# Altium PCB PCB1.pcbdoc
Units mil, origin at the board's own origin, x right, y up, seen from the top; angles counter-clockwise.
Board outline 3937.01 x 3937.01 mil, 2 copper layers (Top Layer, Bottom Layer), stack 62.206 mil thick; 20 components, 19 nets, 119 pads, 8 vias.
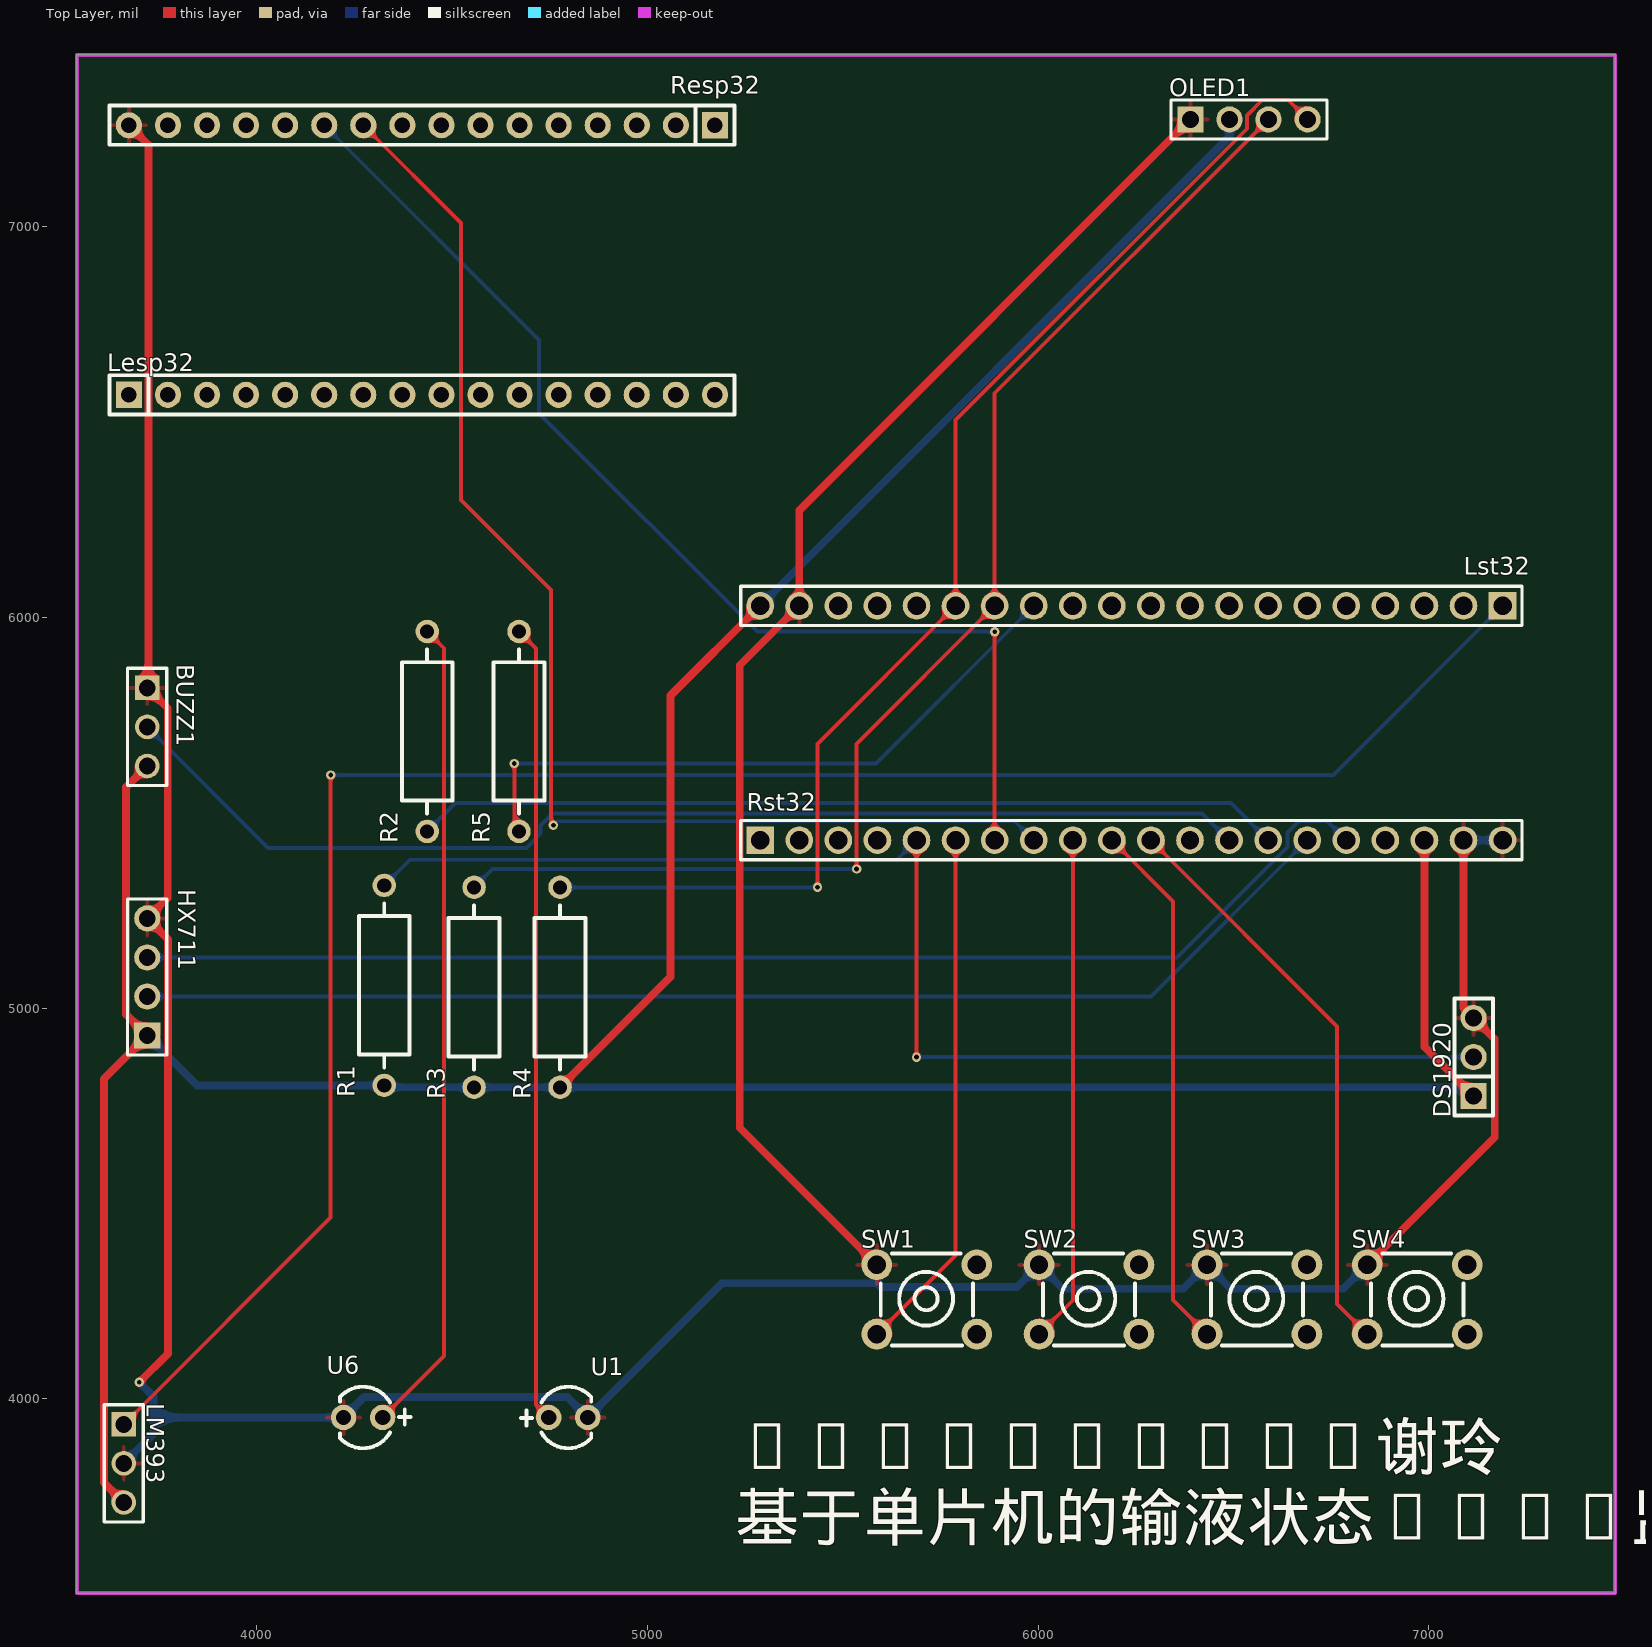
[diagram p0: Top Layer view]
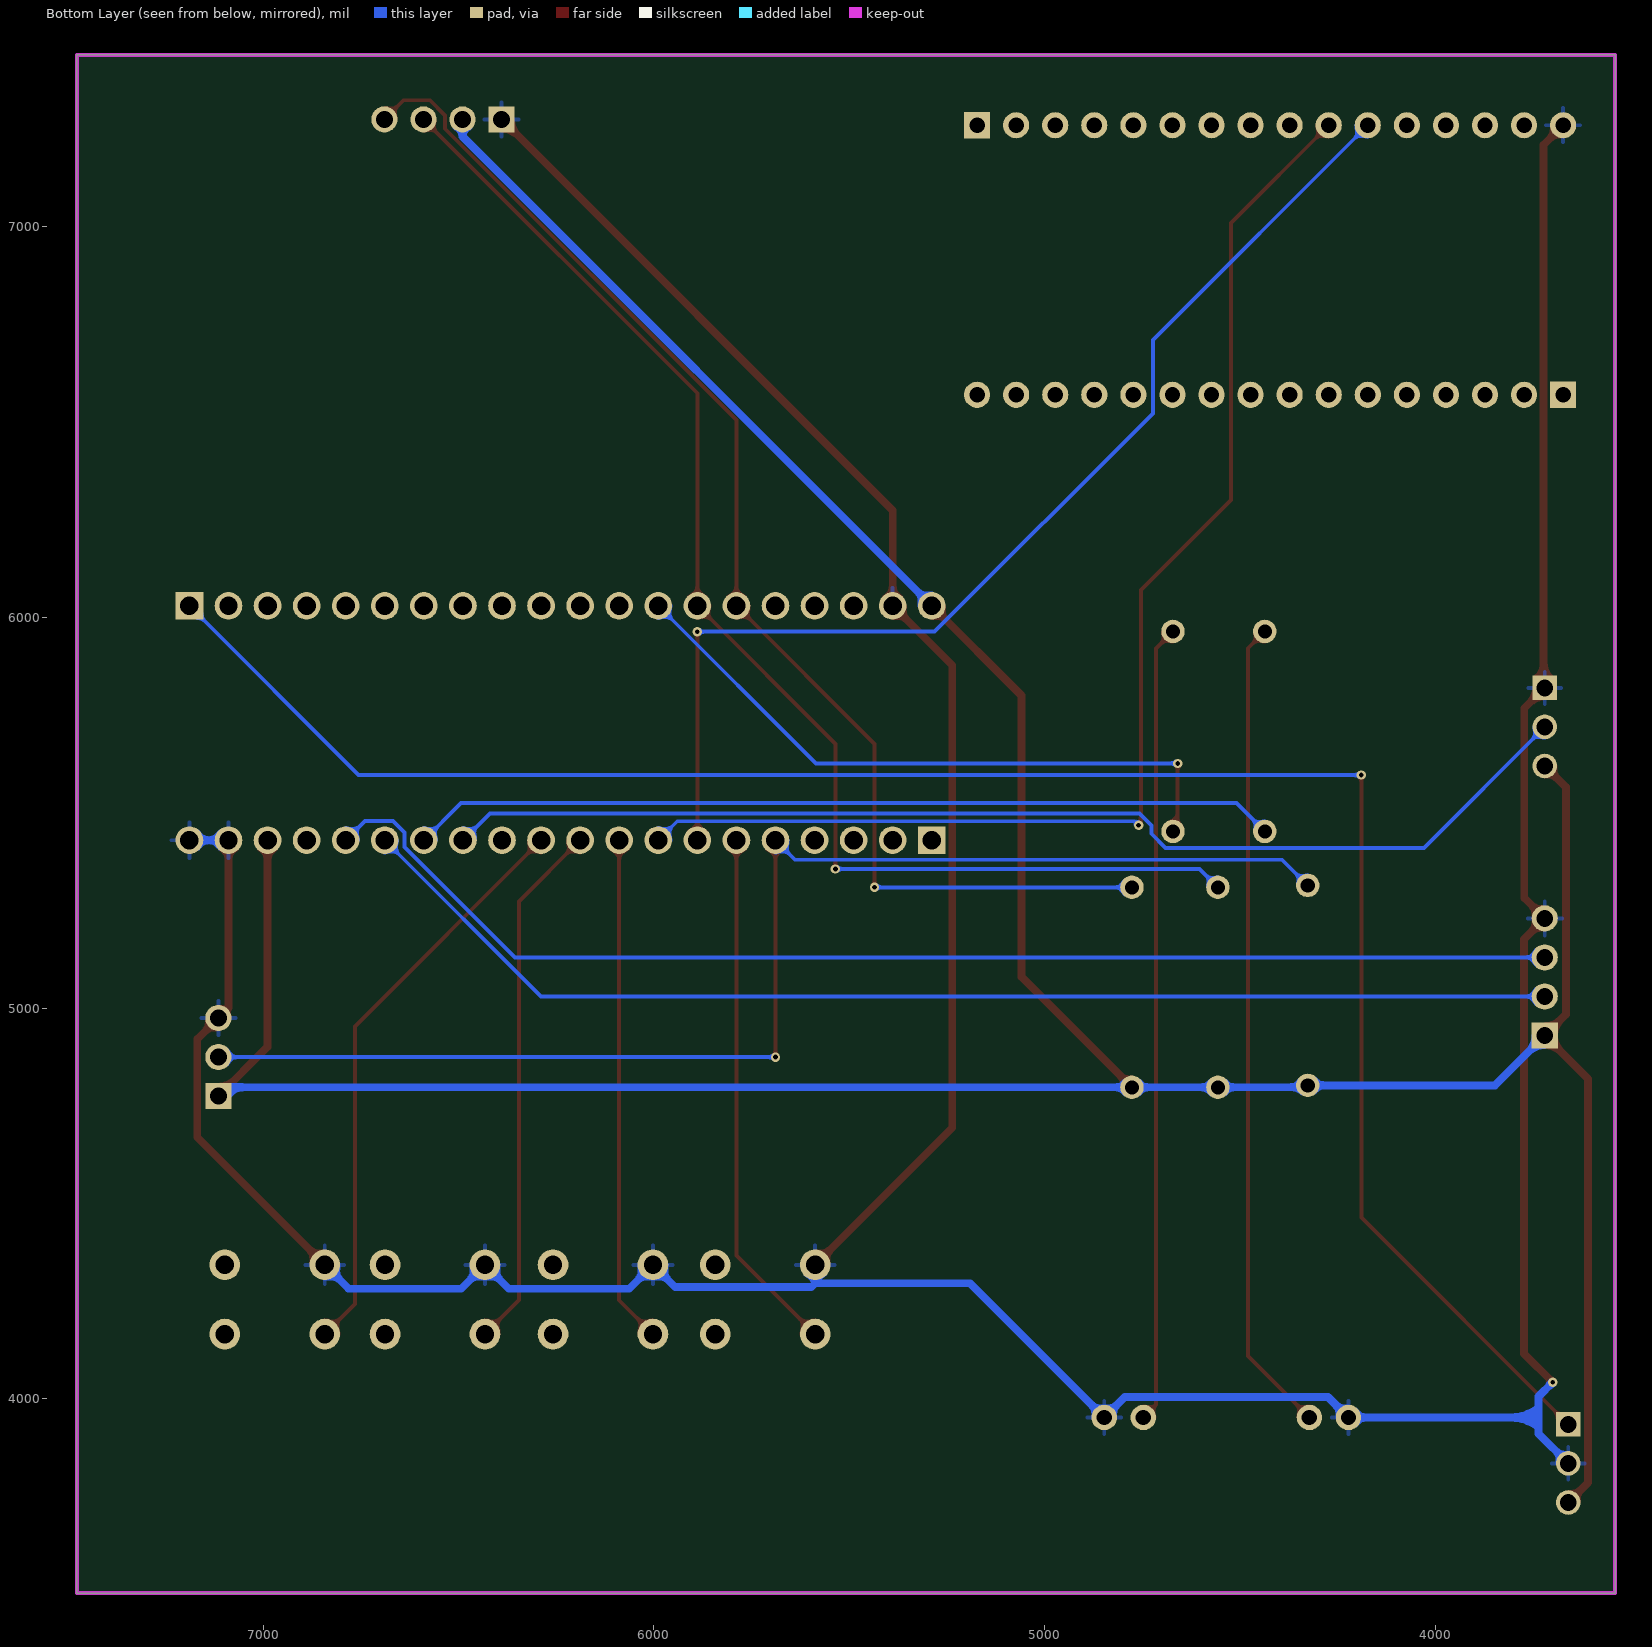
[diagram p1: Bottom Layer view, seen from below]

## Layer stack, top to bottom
Top Solder Mask Layer: solder mask 0.394, Dk 3.3
Top Layer: signal copper 1.379
Dielectric1: surface 59.449, FR4, Dk 4.5
Bottom Layer: signal copper 1.378
Bottom Solder Mask Layer: solder mask 0.394, Dk 3.3

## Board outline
3540,7440 3540,3502.99 7477.01,3502.99 7477.01,7440

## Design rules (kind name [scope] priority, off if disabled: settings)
BoardOutlineClearance copperThickness2oz_1 [All] p2: genericclearance=10 ignorepadtopadclearanceinfootprint=FALSE except(0: Arc-SplitContinuation Track-SplitContinuation SMDPad-SplitContinuation THPad-SplitContinuation Via-SplitContinuation Fill-SplitContinuation Region-SplitContinuation Poly-SplitContinuation Text-SplitContinuation Hole-SplitContinuation; 5.98: Arc-CutoutEdge SMDPad-CutoutEdge THPad-CutoutEdge Via-CutoutEdge Fill-CutoutEdge Region-CutoutEdge Text-CutoutEdge; 6.93: Hole-OutlineEdge Hole-CutoutEdge; 10: Poly-OutlineEdge Poly-CutoutEdge; 11.81: Arc-OutlineEdge Track-OutlineEdge SMDPad-OutlineEdge THPad-OutlineEdge Via-OutlineEdge Fill-OutlineEdge Region-OutlineEdge Text-OutlineEdge Track-CutoutEdge)
BoardOutlineClearance copperThickness1oz_1 [All] p4: genericclearance=8 ignorepadtopadclearanceinfootprint=FALSE except(0: Arc-SplitContinuation Track-SplitContinuation SMDPad-SplitContinuation THPad-SplitContinuation Via-SplitContinuation Fill-SplitContinuation Region-SplitContinuation Poly-SplitContinuation Text-SplitContinuation Hole-SplitContinuation; 6: SMDPad-CutoutEdge THPad-CutoutEdge Via-CutoutEdge Fill-CutoutEdge Region-CutoutEdge Text-CutoutEdge; 6.93: Hole-OutlineEdge Hole-CutoutEdge; 10: Poly-OutlineEdge Poly-CutoutEdge; 11.8: Arc-OutlineEdge Track-OutlineEdge SMDPad-OutlineEdge THPad-OutlineEdge Via-OutlineEdge Fill-OutlineEdge Region-OutlineEdge Text-OutlineEdge; 11.81: Arc-CutoutEdge Track-CutoutEdge)
Clearance copperThickness2oz [(InNet('3V3') OR InNet('GND'))] p1: gap=10 ignorepadtopadclearanceinfootprint=FALSE except(5.98: SMDPad-Track SMDPad-SMDPad THPad-Track SMDPad-THPad THPad-THPad Track-Via SMDPad-Via THPad-Via Via-Via Fill-Track Region-Track Fill-SMDPad Region-SMDPad Fill-THPad Region-THPad Fill-Via Region-Via Fill-Fill Fill-Region Region-Region Arc-Track Arc-SMDPad Arc-THPad Arc-Via Fill-Arc Region-Arc Arc-Arc Text-Track SMDPad-Text Text-THPad Text-Via Fill-Text Region-Text Arc-Text Text-Text; 6.93: Hole-Track Hole-SMDPad Hole-THPad Hole-Via Fill-Hole Region-Hole Hole-Arc Hole-Text)
Clearance copperThickness1oz [All] p3: gap=8 ignorepadtopadclearanceinfootprint=FALSE except(5.98: SMDPad-Track SMDPad-SMDPad THPad-Track SMDPad-THPad THPad-THPad Track-Via SMDPad-Via THPad-Via Via-Via Fill-Track Region-Track Fill-SMDPad Region-SMDPad Fill-THPad Region-THPad Fill-Via Region-Via Fill-Fill Fill-Region Region-Region; 6: Arc-Track Arc-SMDPad Arc-THPad Arc-Via Fill-Arc Region-Arc Arc-Arc Text-Track SMDPad-Text Text-THPad Text-Via Fill-Text Region-Text Arc-Text Text-Text; 6.93: Hole-Track Hole-SMDPad Hole-THPad Hole-Via Fill-Hole Region-Hole Hole-Arc Hole-Text; 10: Poly-Track Poly-SMDPad Poly-THPad Poly-Via Poly-Fill Poly-Region Poly-Poly Poly-Arc Poly-Text Poly-Hole)
Creepage creepage [All] p1: checkdistance=0 ignoreinternallayers=TRUE applytopolygonpour=TRUE
DiffPairsRouting differentialPair [All] p1: maxlimit=6 minlimit=6 mostfreqgap=6 toplayer_minwidth=5 toplayer_prefwidth=10 toplayer_maxwidth=100 toplayer_mingap=6 toplayer_prefgap=6 toplayer_maxgap=6 bottomlayer_minwidth=5 bottomlayer_prefwidth=10 bottomlayer_maxwidth=100 bottomlayer_mingap=6 bottomlayer_prefgap=6 bottomlayer_maxgap=6 maxuncoupledlength=10
HoleToHoleClearance otherClearance [All] p1: gap=11.81 allowstackedmicrovias=TRUE
Length netLength [All] p1: minlimit=0 maxlimit=0
MatchedLengths netLengthTolerance [All] p1: tolerance=1000
PasteMaskExpansion pasteMaskExpansion [All] p1: expansion=0
PlaneConnect innerPlane [All] p1: planeconnectstyle=Relief reliefexpansion=20 reliefentries=4 reliefconductorwidth=10 reliefairgap=10
PolygonConnect copperRegion [(InNet('GND'))] p1: connectstyle=Relief reliefconductorwidth=10 reliefentries=4 polygonreliefangle="90 Angle" airgapwidth=10 via.connectstyle=Relief via.reliefconductorwidth=10 via.reliefentries=4 via.polygonreliefangle="90 Angle" via.airgapwidth=10
RoutingVias viaSize [All] p1: holewidth=12.01 width=24.02 viastyle="Through Hole" minholewidth=11.81 minwidth=19.68 maxholewidth=248.03 maxwidth=393.7
SolderMaskExpansion solderMaskExpansion [IsVia] p1: expansion=-1000 istentingtop=TRUE
SolderMaskExpansion solderMaskExpansion [All] p2: expansion=2 istentingtop=FALSE
Width copperThickness2oz_2 [(InNet('3V3') OR InNet('GND'))] p1: maxlimit=10 minlimit=10 preferedwidth=10 toplayer_minwidth=20 toplayer_maxwidth=100 toplayer_prefwidth=20 bottomlayer_minwidth=20 bottomlayer_maxwidth=100 bottomlayer_prefwidth=20
Width copperThickness1oz_2 [All] p2: maxlimit=10 minlimit=10 preferedwidth=10 toplayer_minwidth=10 toplayer_maxwidth=100 toplayer_prefwidth=10 bottomlayer_minwidth=10 bottomlayer_maxwidth=100 bottomlayer_prefwidth=10

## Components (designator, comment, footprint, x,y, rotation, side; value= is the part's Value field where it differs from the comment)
BUZZ1 "PIN3" HDR-TH_3P-P2.54-V-M-1 3720,5720 r270 top
DS1920 "DS1920" HDR-TH_3P-P2.54-V-M 7115,4875 r90 top
HX711 "HX711" HDR-TH_4P-P2.54-V-M-1 3720,5080 r90 top
Lesp32 "Lesp32" HDR-TH_1X16P 4422.96,6570 r0 top
LM393 "LM393" HDR-TH_3P-P2.54-V-M-1 3660,3835 r270 top
Lst32 "Lst32" HDR-TH_HMT-PM254-1X20Z-H85 6239,6030 r180 top
OLED1 "2.54-1*4" HDR-TH_4P-P2.54-V-M-1 6540,7275 r0 top
R1 "4.7kΩ" RES-TH_BD3.3-L9.0-P13.00-D0.6 4326.6,5058.4 r90 top
R2 "220Ω" RES-TH_BD3.3-L9.0-P13.00-D0.6 4436.6,5708.4 r90 top
R3 "4.7kΩ" RES-TH_BD3.3-L9.0-P13.00-D0.6 4556.6,5053.4 r90 top
R4 "4.7kΩ" RES-TH_BD3.3-L9.0-P13.00-D0.6 4776.6,5053.4 r90 top
R5 "220Ω" RES-TH_BD3.3-L9.0-P13.00-D0.6 4671.6,5708.4 r90 top
Resp32 "Resp32" HDR-TH_1X16P 4423.04,7260 r180 top
Rst32 "Rst32" HDR-TH_HMT-PM254-1X20Z-H85 6239,5430 r0 top
SW1 "轻触开关6*6*4.5" KEY-TH_4P-L6.0-W6.0-P4.50-LS7.5 5715.45,4254.55 r0 top
SW2 "轻触开关6*6*4.5" KEY-TH_4P-L6.0-W6.0-P4.50-LS7.5 6130.45,4254.55 r0 top
SW3 "轻触开关6*6*4.5" KEY-TH_4P-L6.0-W6.0-P4.50-LS7.5 6560.45,4254.55 r0 top
SW4 "轻触开关6*6*4.5" KEY-TH_4P-L6.0-W6.0-P4.50-LS7.5 6970.45,4254.55 r0 top
U1 "LED_YELLOW" LED-TH_BD4.0-P2.54-FD_RED 4797.5,3952.5 r0 top
U6 "LED_RED" LED-TH_BD4.0-P2.54-FD_RED 4272.5,3952.5 r180 top

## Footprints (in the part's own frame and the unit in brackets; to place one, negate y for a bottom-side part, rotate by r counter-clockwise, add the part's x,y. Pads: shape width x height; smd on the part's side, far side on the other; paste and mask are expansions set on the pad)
HDR-TH_1X16P [mm]
  rect 1.7x1.7 hole 1 paste+0 mask+0.051: 1(-19.05,0)
  round 1.7 hole 1 paste+0 mask+0.051: 2(-16.51,0) 3(-13.97,0) 4(-11.43,0) 5(-8.89,0) 6(-6.35,0) 7(-3.81,0) 8(-1.27,0) 9(1.27,0) 10(3.81,0) 11(6.35,0) 12(8.89,0) 13(11.43,0) 14(13.97,0) 15(16.51,0) 16(19.05,0)
  silkscreen extent -20.32,-1.27 20.32,1.27
HDR-TH_3P-P2.54-V-M [mm]
  rect 1.7x1.7 hole 1.1: 1(-2.54,0)
  round 1.7 hole 1.1: 2(0,0) 3(2.54,0)
  silkscreen extent -3.81,-1.25 3.81,1.25
HDR-TH_3P-P2.54-V-M-1 [mm]
  rect 1.575x1.6 hole 1.1 paste+0 mask+0.05: 1(-2.54,0)
  round 1.6 hole 1.1 paste+0 mask+0.05: 2(0,0) 3(2.54,0)
  silkscreen extent -3.81,-1.27 3.81,1.27
HDR-TH_4P-P2.54-V-M-1 [mm]
  rect 1.7x1.7 hole 1.1: 1(-3.81,0)
  round 1.7 hole 1.1: 2(-1.27,0) 3(1.27,0) 4(3.81,0)
  silkscreen extent -5.08,-1.27 5.08,1.27
HDR-TH_HMT-PM254-1X20Z-H85 [mm]
  rect 1.8x1.8 hole 1.2: 1(-24.13,0)
  round 1.8 hole 1.2: 2(-21.59,0) 3(-19.05,0) 4(-16.51,0) 5(-13.97,0) 6(-11.43,0) 7(-8.89,0) 8(-6.35,0) 9(-3.81,0) 10(-1.27,0) 11(1.27,0) 12(3.81,0) 13(6.35,0) 14(8.89,0) 15(11.43,0) 16(13.97,0) 17(16.51,0) 18(19.05,0) 19(21.59,0) 20(24.13,0)
  silkscreen extent -25.4,-1.27 25.4,1.27
KEY-TH_4P-L6.0-W6.0-P4.50-LS7.5 [mm]
  round 2 hole 1.2: 1(-3.25,-2.25) 2(3.25,-2.25) 3(3.25,2.25) 4(-3.25,2.25)
  silkscreen extent -3,-3 3,3
LED-TH_BD4.0-P2.54-FD_RED [mil]
  round 65 hole 39.37: 1(-50,0) 2(50,0)
  silkscreen extent -122,-79 59,79
RES-TH_BD3.3-L9.0-P13.00-D0.6 [mil]
  round 60 hole 36: 1(-255.91,0) 2(255.9,0)
  silkscreen extent -210,-65 210,65

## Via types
v1: diameter 24.02, hole 12, Top Layer to Bottom Layer, 8 vias

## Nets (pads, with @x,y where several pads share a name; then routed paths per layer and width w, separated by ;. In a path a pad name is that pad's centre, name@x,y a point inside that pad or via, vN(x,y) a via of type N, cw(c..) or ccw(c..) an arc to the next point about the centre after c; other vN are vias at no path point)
3V3: BUZZ1.3 DS1920.1 HX711.1 LM393.3 Lst32.20 OLED1.2 R1.1 R3.1 R4.1 Rst32.18 | length 9350.6
  Top Layer w20: LM393.3 3609.03,3785.97 3609.03,4819.03 HX711.1 3665.85,4984.15 3665.85,5565.85 BUZZ1.3 ; R4.1 5059.27,5080.18 5059.27,5800.27 Lst32.20 ; Rst32.18 6989,4901.01 DS1920.1
  Bottom Layer w20: HX711.1 3847.5,4802.5 R1.1 4331.59,4797.5 R3.1 R4.1 7092.5,4797.5 DS1920.1 ; Lst32.20 6490,7231 OLED1.2
$1N10: R2.2 U6.1 | length 2094.8
  Top Layer w10: U6.1 4479.68,4109.68 4479.68,5921.22 R2.2
$1N63: R5.2 U1.1 | length 2043.3
  Top Layer w10: R5.2 4714.95,5920.95 4714.95,3985.05 U1.1
BUZZ: BUZZ1.2 Rst32.13 | length 2974.9
  Bottom Layer w10: BUZZ1.2 4029.48,5410.52 4690.26,5410.52 4726.22,5446.48 4726.22,5468.02 4757.02,5498.82 6420.18,5498.82 Rst32.13
DS_DQ: DS1920.2 R1.2 Rst32.5 | length 3391.3
  Top Layer w10: v1(5689,4875) Rst32.5
  Bottom Layer w10: R1.2 4392.16,5379.89 5638.88,5379.89 Rst32.5 ; v1(5689,4875) DS1920.2
GND: BUZZ1.1 DS1920.3 HX711.4 LM393.2 Lst32.19 OLED1.1 Resp32.16 Rst32.19 Rst32.20 SW1.4 SW2.4 SW3.4 SW4.4 U1.2 U6.2 | length 11967.5
  Top Layer w20: Resp32.16 3722.96,7210.08 3722.96,5822.96 BUZZ1.1 3772.43,5767.57 3772.43,5282.43 HX711.4 3773.31,5176.69 3773.31,4115.82 v1(3699.94,4042.45) ; SW1.4 5236.48,4694.15 5236.48,5877.48 Lst32.19 5389,6274 OLED1.1 ; SW4.4 7169.17,4669.81 7169.17,4920.83 DS1920.3 7088.99,5001.01 Rst32.19
  Bottom Layer w20: LM393.2 3736,3911 3736,3952.5 ; v1(3699.94,4042.45) 3736,4006.39 3736,3952.5 ; SW1.4 5587.5,4296.04 ; SW4.4 6781.6,4282.23 6493.4,4282.23 SW3.4 6371.6,4282.23 6063.4,4282.23 SW2.4 5945.59,4286.22 5597.32,4286.22 5587.5,4296.04 ; Rst32.19 Rst32.20 ; 3736,3952.5 U6.2 4274.9,4004.9 4795.1,4004.9 U1.2 5191.04,4296.04 5587.5,4296.04
HX_DT: HX711.3 Rst32.16 | length 3255.7
  Bottom Layer w10: HX711.3 6356.19,5130 6639,5412.81 6639,5449.97 6668.08,5479.05 6739.95,5479.05 Rst32.16
HX_SCK: HX711.2 Rst32.15 | length 3134.7
  Bottom Layer w10: HX711.2 6288.99,5030 Rst32.15
I2C_SCL: Lst32.14 OLED1.3 R3.2 | length 3353.9
  Top Layer w10: v1(5535.58,5356.39) 5535.58,5676.58 Lst32.14 5889,6574 OLED1.3
  Bottom Layer w10: R3.2 4603.66,5356.39 v1(5535.58,5356.39)
I2C_SDA: Lst32.15 OLED1.4 R4.2 | length 3281.5
  Top Layer w10: v1(5435.58,5309.32) 5435.58,5676.58 Lst32.15 5789,6505.3 6534.61,7250.91 6534.61,7284.8 6573.7,7323.89 6641.11,7323.89 OLED1.4
  Bottom Layer w10: R4.2 v1(5435.58,5309.32)
IR_OUT: LM393.1 Lst32.1 | length 5060.1
  Top Layer w10: LM393.1 4189.45,4464.45 v1(4189.45,5596.76)
  Bottom Layer w10: v1(4189.45,5596.76) 6755.76,5596.76 Lst32.1
KEY1: Rst32.6 SW1.1 | length 1347.5
  Top Layer w10: SW1.1 5789,4367.47 Rst32.6
KEY2: Rst32.9 SW2.1 | length 1299.9
  Top Layer w10: SW2.1 6089,4252.47 Rst32.9
KEY3: Rst32.10 SW3.1 | length 1364.9
  Top Layer w10: Rst32.10 6345.46,5273.55 6345.46,4253.01 SW3.1
KEY4: Rst32.11 SW4.1 | length 1493.3
  Top Layer w10: Rst32.11 6765.46,4953.55 6765.46,4243.01 SW4.1
LED_R: R2.1 Rst32.14 | length 2222
  Bottom Layer w10: R2.1 4509.37,5525.27 6493.73,5525.27 Rst32.14
LED_Y: Lst32.13 R5.1 | length 1675.6
  Top Layer w10: v1(4659.53,5626.47) 4659.53,5464.55 R5.1
  Bottom Layer w10: v1(4659.53,5626.47) 5585.47,5626.47 Lst32.13
USART2_RX: Resp32.10 Rst32.8 | length 3246.4
  Top Layer w10: Resp32.10 4522.96,7010.08 4522.96,6301.21 4753.85,6070.32 4753.85,5474.44 v1(4759.63,5468.66)
  Bottom Layer w10: v1(4759.63,5468.66) 4769.48,5478.51 5940.49,5478.51 Rst32.8
USART2_TX: Resp32.11 Rst32.7 | length 2896.5
  Top Layer w10: Rst32.7 v1(5889,5963.78)
  Bottom Layer w10: Resp32.11 4722.96,6710.08 4722.96,6522.49 5281.67,5963.78 v1(5889,5963.78)
pads on no net: Lesp32.1 Lesp32.2 Lesp32.3 Lesp32.4 Lesp32.5 Lesp32.6 Lesp32.7 Lesp32.8 Lesp32.9 Lesp32.10 Lesp32.11 Lesp32.12 Lesp32.13 Lesp32.14 Lesp32.15 Lesp32.16 Lst32.2 Lst32.3 Lst32.4 Lst32.5 Lst32.6 Lst32.7 Lst32.8 Lst32.9 Lst32.10 Lst32.11 Lst32.12 Lst32.16 Lst32.17 Lst32.18 Resp32.1 Resp32.2 Resp32.3 Resp32.4 Resp32.5 Resp32.6 Resp32.7 Resp32.8 Resp32.9 Resp32.12 Resp32.13 Resp32.14 Resp32.15 Rst32.1 Rst32.2 Rst32.3 Rst32.4 Rst32.12 Rst32.17 SW1.2 SW1.3 SW2.2 SW2.3 SW3.2 SW3.3 SW4.2 SW4.3

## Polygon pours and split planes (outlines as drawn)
GND on Bottom Layer (solid, remove dead copper, pour order 2): 3000,7695 3000,3000 8345,3000 8345,7695
GND on Top Layer (solid, remove dead copper, pour order 0): 3105,7740 3105,3165 7990,3165 7990,7740

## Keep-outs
Board Outline Layer:
  the board outline again, w10

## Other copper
Top Layer:
  region net 3V3: 3696.75,5582.61 3682.61,5596.75 3683.88,5598.13 3684.94,5599.52 3685.82,5600.91 3686.54,5602.33 3687.54,5605.23 3688.09,5608.23 3688.33,5611.38 3688.39,5614.7 3688.42,5618.22 3688.57,5621.97 3721.97,5588.57 3718.22,5588.42 3714.7,5588.39 3711.38,5588.33 3708.23,5588.09 3705.22,5587.54 3702.33,5586.54 3700.91,5585.82 3699.51,5584.94 3698.13,5583.88
  region net GND: 3712.96,5881 3732.96,5881 3733.29,5876.05 3734.27,5871.18 3735.89,5866.49 3738.11,5862.05 3740.89,5857.94 3744.2,5854.23 3747.96,5851 3697.96,5851 3701.73,5854.23 3705.03,5857.94 3707.82,5862.05 3710.04,5866.49 3711.66,5871.18 3712.63,5876.05 3712.96,5881
  region net GND: 3762.1,5792.05 3747.47,5778.39 3742.75,5781.56 3737.71,5784.19 3732.42,5786.28 3726.94,5787.78 3721.33,5788.7 3715.65,5789 3751.5,5823.87 3751.8,5818.19 3752.71,5812.58 3754.22,5807.1 3756.3,5801.81 3758.94,5796.77 3762.1,5792.05
  region net 3V3: 7070.93,4804.93 7085.07,4819.07 7089.8,4815.91 7094.83,4813.27 7100.12,4811.19 7105.6,4809.68 7111.22,4808.77 7116.89,4808.46 7081.54,4773.11 7081.23,4778.79 7080.32,4784.4 7078.81,4789.88 7076.73,4795.17 7074.09,4800.21 7070.93,4804.93
  region net GND: 7081.92,4993.94 7096.07,5008.08 7096.72,5007.58 7097.51,5007.23 7099.47,5006.9 7101.86,5006.96 7104.59,5007.28 7110.7,5008.14 7113.91,5008.41 7117.1,5008.4 7081.6,4972.9 7081.59,4976.09 7081.86,4979.3 7082.72,4985.41 7083.04,4988.14 7083.1,4990.53 7082.77,4992.49 7082.42,4993.28
  region net GND: 7154.29,4949.86 7140.15,4935.71 7138.66,4937.07 7137.17,4938.2 7135.66,4939.12 7134.13,4939.86 7132.58,4940.43 7131,4940.86 7127.74,4941.35 7124.33,4941.51 7120.75,4941.5 7116.95,4941.47 7112.9,4941.6 7148.4,4977.1 7148.53,4973.05 7148.5,4969.25 7148.49,4965.67 7148.65,4962.26 7149.14,4959.01 7149.57,4957.43 7150.14,4955.87 7150.88,4954.34 7151.8,4952.83 7152.93,4951.34
  region net 3V3: 3690.08,4885.93 3675.93,4900.06 3679.09,4904.79 3681.73,4909.82 3683.81,4915.11 3685.32,4920.6 3686.23,4926.21 3686.54,4931.88 3721.9,4896.54 3716.22,4896.23 3710.61,4895.32 3705.13,4893.81 3699.84,4891.73 3694.8,4889.09 3690.08,4885.93
  region net 3V3: 3675.93,4959.93 3690.07,4974.07 3694.79,4970.91 3699.83,4968.27 3705.12,4966.19 3710.6,4964.68 3716.21,4963.77 3721.89,4963.46 3686.54,4928.11 3686.23,4933.79 3685.32,4939.4 3683.81,4944.88 3681.73,4950.17 3679.09,4955.2 3675.93,4959.93
  region net GND: 3745.15,5269.29 3759.29,5255.14 3757.93,5253.66 3756.8,5252.16 3755.88,5250.65 3755.14,5249.12 3754.57,5247.57 3754.14,5245.99 3753.65,5242.73 3753.49,5239.33 3753.51,5235.74 3753.53,5231.94 3753.4,5227.9 3717.91,5263.4 3721.95,5263.53 3725.75,5263.5 3729.34,5263.49 3732.75,5263.65 3736,5264.14 3737.58,5264.57 3739.13,5265.14 3740.66,5265.87 3742.17,5266.8 3743.67,5267.93
  region net GND: 3759.29,5204.85 3745.14,5190.71 3743.66,5192.07 3742.17,5193.2 3740.66,5194.12 3739.13,5194.86 3737.57,5195.43 3735.99,5195.86 3732.74,5196.35 3729.33,5196.51 3725.74,5196.5 3721.95,5196.47 3717.9,5196.6 3753.4,5232.09 3753.53,5228.05 3753.5,5224.25 3753.49,5220.66 3753.65,5217.26 3754.14,5214 3754.57,5212.42 3755.14,5210.87 3755.88,5209.34 3756.8,5207.83 3757.93,5206.34
  region net 3V3: 3622.61,3758.25 3636.75,3772.39 3638.13,3771.12 3639.52,3770.06 3640.92,3769.18 3642.33,3768.46 3645.23,3767.46 3648.23,3766.91 3651.38,3766.67 3654.7,3766.61 3658.22,3766.58 3661.97,3766.43 3628.57,3733.03 3628.42,3736.78 3628.39,3740.3 3628.33,3743.62 3628.09,3746.77 3627.54,3749.78 3626.54,3752.67 3625.82,3754.09 3624.94,3755.49 3623.88,3756.87
  region net IR_OUT: 3689.24,3971.3 3696.8,3964.72 3694.52,3961.12 3692.86,3957.2 3691.84,3953.06 3691.5,3948.81 3673.33,3966 3677.57,3966.34 3681.71,3967.36 3685.63,3969.03 3689.24,3971.3
  region net 3V3: 5261.96,5988.82 5247.82,6002.96 5249.27,6004.55 5250.46,6006.16 5251.42,6007.78 5252.18,6009.42 5252.76,6011.09 5253.17,6012.79 5253.61,6016.29 5253.69,6019.96 5253.6,6023.81 5253.52,6027.89 5253.64,6032.22 5291.21,5994.63 5286.88,5994.52 5282.81,5994.6 5278.95,5994.69 5275.28,5994.61 5271.78,5994.17 5270.08,5993.76 5268.41,5993.18 5266.77,5992.42 5265.15,5991.46 5263.54,5990.26
  region net GND: 5361.95,5988.82 5347.82,6002.96 5349.27,6004.55 5350.46,6006.16 5351.42,6007.78 5352.18,6009.42 5352.76,6011.09 5353.17,6012.79 5353.61,6016.29 5353.69,6019.96 5353.6,6023.81 5353.52,6027.89 5353.64,6032.22 5391.21,5994.63 5386.88,5994.52 5382.81,5994.6 5378.95,5994.69 5375.28,5994.61 5371.78,5994.17 5370.08,5993.76 5368.41,5993.18 5366.77,5992.42 5365.15,5991.46 5363.54,5990.26
  region net GND: 5379,6078.24 5399,6078.24 5399.1,6076.09 5399.39,6074.11 5399.85,6072.29 5400.48,6070.59 5401.25,6069 5402.16,6067.51 5404.33,6064.72 5406.86,6062.07 5409.65,6059.41 5412.6,6056.58 5415.57,6053.44 5362.43,6053.43 5365.4,6056.58 5368.34,6059.41 5371.14,6062.07 5373.67,6064.72 5375.84,6067.5 5376.74,6069 5377.52,6070.59 5378.15,6072.28 5378.61,6074.11 5378.9,6076.09
  region net I2C_SDA: 5758.42,5992.35 5751.35,5999.43 5752.75,6001.03 5753.82,6002.71 5754.6,6004.44 5755.13,6006.24 5755.43,6008.1 5755.54,6010.03 5755.33,6014.05 5754.11,6022.74 5753.65,6027.39 5753.57,6029.78 5753.64,6032.22 5791.21,5994.63 5788.77,5994.57 5786.38,5994.64 5781.73,5995.11 5773.04,5996.33 5769.02,5996.54 5767.09,5996.43 5765.23,5996.13 5763.43,5995.6 5761.69,5994.82 5760.02,5993.75
  region net I2C_SDA: 5784,6078.24 5794,6078.24 5794.14,6076.12 5794.57,6074.18 5795.24,6072.4 5796.15,6070.75 5797.25,6069.22 5798.53,6067.79 5801.52,6065.09 5808.53,6059.81 5812.15,6056.85 5813.9,6055.21 5815.57,6053.44 5762.42,6053.43 5764.1,6055.21 5765.85,6056.84 5769.46,6059.8 5776.47,6065.09 5779.47,6067.78 5780.75,6069.22 5781.85,6070.75 5782.75,6072.39 5783.43,6074.17 5783.85,6076.11
  region net I2C_SCL: 5858.42,5992.35 5851.35,5999.43 5852.75,6001.03 5853.82,6002.71 5854.6,6004.44 5855.13,6006.24 5855.43,6008.1 5855.54,6010.03 5855.33,6014.05 5854.11,6022.74 5853.65,6027.39 5853.57,6029.78 5853.64,6032.22 5891.21,5994.63 5888.77,5994.57 5886.38,5994.64 5881.73,5995.11 5873.04,5996.33 5869.02,5996.54 5867.09,5996.43 5865.23,5996.13 5863.43,5995.6 5861.69,5994.82 5860.02,5993.75
  region net I2C_SCL: 5884,6078.24 5894,6078.24 5894.14,6076.12 5894.57,6074.18 5895.24,6072.4 5896.15,6070.75 5897.25,6069.22 5898.53,6067.79 5901.52,6065.09 5908.53,6059.81 5912.15,6056.85 5913.9,6055.21 5915.57,6053.44 5862.42,6053.43 5864.1,6055.21 5865.85,6056.84 5869.46,6059.8 5876.47,6065.09 5879.46,6067.78 5880.75,6069.22 5881.85,6070.75 5882.75,6072.39 5883.43,6074.17 5883.85,6076.11
  region net GND: 6360.07,7230.93 6345.93,7245.07 6349.09,7249.8 6351.73,7254.83 6353.81,7260.12 6355.32,7265.61 6356.23,7271.22 6356.54,7276.89 6391.89,7241.54 6386.21,7241.23 6380.6,7240.32 6375.12,7238.81 6369.83,7236.73 6364.79,7234.09 6360.07,7230.93
  region net I2C_SCL: 6561.32,7239.25 6554.25,7246.32 6555.57,7247.84 6556.6,7249.42 6557.35,7251.05 6557.85,7252.75 6558.15,7254.5 6558.28,7256.3 6558.11,7260.07 6557.02,7268.21 6556.6,7272.56 6556.6,7277.1 6592.09,7241.6 6587.56,7241.6 6583.2,7242.02 6575.06,7243.11 6571.29,7243.28 6569.49,7243.16 6567.74,7242.86 6566.05,7242.35 6564.41,7241.6 6562.83,7240.58
  region net I2C_SDA: 6654.25,7303.68 6661.32,7310.75 6662.83,7309.42 6664.41,7308.4 6666.05,7307.65 6667.74,7307.14 6669.49,7306.84 6671.29,7306.72 6675.06,7306.89 6683.2,7307.98 6687.56,7308.4 6692.09,7308.4 6656.6,7272.9 6656.6,7277.44 6657.02,7281.79 6658.11,7289.93 6658.28,7293.7 6658.15,7295.5 6657.85,7297.25 6657.35,7298.95 6656.6,7300.58 6655.57,7302.16
  region net $1N10: 4469.01,5938.97 4461.94,5931.89 4460.57,5933.1 4459.16,5934.03 4457.7,5934.73 4456.2,5935.21 4454.65,5935.51 4453.05,5935.65 4449.73,5935.56 4442.57,5934.7 4438.73,5934.36 4434.72,5934.37 4466.54,5966.19 4466.55,5962.18 4466.2,5958.34 4465.34,5951.17 4465.26,5947.85 4465.4,5946.26 4465.7,5944.71 4466.18,5943.2 4466.87,5941.75 4467.81,5940.33
  region net 3V3: 4798.4,4833.45 4812.55,4819.31 4810.33,4816.71 4808.78,4814.06 4807.77,4811.35 4807.18,4808.53 4806.88,4805.58 4806.76,4802.47 4806.54,4795.62 4774.72,4827.44 4781.56,4827.67 4784.68,4827.79 4787.63,4828.08 4790.44,4828.67 4793.16,4829.68 4795.8,4831.23
  region net $1N63: 4704.01,5938.96 4696.94,5931.89 4695.57,5933.1 4694.16,5934.03 4692.7,5934.73 4691.2,5935.21 4689.65,5935.51 4688.05,5935.65 4684.73,5935.56 4677.57,5934.7 4673.73,5934.36 4669.72,5934.37 4701.54,5966.19 4701.55,5962.18 4701.2,5958.34 4700.34,5951.17 4700.26,5947.85 4700.4,5946.26 4700.7,5944.71 4701.18,5943.2 4701.87,5941.74 4702.81,5940.33
  region net LED_Y: 4654.53,5482.62 4664.53,5500.72 4664.64,5498.64 4664.95,5496.71 4665.45,5494.92 4666.14,5493.26 4666.99,5491.72 4668.01,5490.29 4669.16,5488.96 4670.46,5487.71 4673.4,5485.45 4676.73,5483.42 4680.37,5481.54 4684.22,5479.72 4643.01,5461.62 4644.35,5464.94 4646.04,5468.06 4647.94,5470.98 4649.87,5473.7 4651.66,5476.23 4653.14,5478.55 4654.16,5480.68 4654.43,5481.68
  region net GND: 3712.33,7234.86 3698.19,7220.71 3696.71,7222.07 3695.21,7223.2 3693.7,7224.12 3692.17,7224.86 3690.62,7225.43 3689.04,7225.85 3685.79,7226.35 3682.38,7226.51 3678.79,7226.49 3674.99,7226.47 3670.95,7226.6 3706.44,7262.1 3706.57,7258.06 3706.55,7254.26 3706.53,7250.67 3706.69,7247.26 3707.18,7244.01 3707.61,7242.43 3708.18,7240.88 3708.92,7239.35 3709.84,7237.84 3710.97,7236.34
  region net USART2_RX: 4308.79,7231.32 4301.72,7224.25 4300.21,7225.57 4298.63,7226.59 4296.99,7227.35 4295.3,7227.85 4293.55,7228.15 4291.75,7228.28 4287.98,7228.11 4279.84,7227.02 4275.48,7226.6 4270.95,7226.6 4306.44,7262.1 4306.44,7257.56 4306.02,7253.21 4304.93,7245.06 4304.76,7241.3 4304.89,7239.49 4305.19,7237.74 4305.69,7236.05 4306.44,7234.42 4307.47,7232.84
  region net GND: 7098.99,5381.76 7078.99,5381.77 7078.9,5383.91 7078.61,5385.89 7078.14,5387.72 7077.52,5389.42 7076.74,5391 7075.83,5392.5 7073.67,5395.29 7071.13,5397.93 7068.34,5400.6 7065.4,5403.42 7062.42,5406.57 7115.57,5406.56 7112.59,5403.42 7109.65,5400.59 7106.86,5397.93 7104.32,5395.28 7102.16,5392.49 7101.25,5391 7100.47,5389.41 7099.85,5387.71 7099.38,5385.88 7099.09,5383.91
  region net 3V3: 6999,5381.76 6979,5381.77 6978.9,5383.91 6978.61,5385.89 6978.14,5387.72 6977.52,5389.42 6976.74,5391 6975.83,5392.5 6973.67,5395.28 6971.13,5397.93 6968.34,5400.59 6965.4,5403.42 6962.42,5406.57 7015.57,5406.56 7012.59,5403.42 7009.65,5400.59 7006.86,5397.93 7004.32,5395.28 7002.16,5392.49 7001.25,5391 7000.48,5389.41 6999.85,5387.71 6999.38,5385.88 6999.09,5383.91
  region net KEY4: 6326.65,5399.43 6319.57,5392.36 6317.97,5393.75 6316.3,5394.82 6314.56,5395.61 6312.76,5396.13 6310.9,5396.43 6308.98,5396.54 6304.96,5396.33 6296.26,5395.11 6291.61,5394.65 6289.22,5394.57 6286.78,5394.64 6324.36,5432.22 6324.43,5429.78 6324.35,5427.39 6323.89,5422.74 6322.67,5414.04 6322.46,5410.02 6322.57,5408.1 6322.87,5406.24 6323.4,5404.44 6324.18,5402.7 6325.25,5401.03
  region net KEY3: 6226.65,5399.43 6219.58,5392.36 6217.97,5393.75 6216.3,5394.83 6214.56,5395.61 6212.76,5396.13 6210.9,5396.43 6208.98,5396.54 6204.96,5396.33 6196.26,5395.11 6191.61,5394.65 6189.22,5394.57 6186.78,5394.64 6224.36,5432.22 6224.43,5429.78 6224.35,5427.39 6223.89,5422.74 6222.67,5414.04 6222.46,5410.02 6222.57,5408.1 6222.87,5406.24 6223.4,5404.44 6224.18,5402.7 6225.25,5401.03
  region net KEY2: 6094,5381.76 6084,5381.76 6083.85,5383.89 6083.43,5385.83 6082.75,5387.61 6081.85,5389.25 6080.75,5390.78 6079.46,5392.22 6076.47,5394.91 6069.46,5400.2 6065.85,5403.15 6064.1,5404.79 6062.42,5406.57 6115.57,5406.56 6113.9,5404.79 6112.15,5403.15 6108.53,5400.19 6101.52,5394.91 6098.53,5392.21 6097.25,5390.78 6096.15,5389.25 6095.24,5387.6 6094.57,5385.82 6094.14,5383.88
  region net USART2_TX: 5884,5478.24 5894,5478.24 5894.14,5476.12 5894.57,5474.18 5895.24,5472.4 5896.15,5470.76 5897.25,5469.23 5898.53,5467.79 5901.52,5465.1 5908.53,5459.81 5912.15,5456.85 5913.9,5455.21 5915.57,5453.44 5862.42,5453.44 5864.1,5455.21 5865.85,5456.85 5869.46,5459.81 5876.47,5465.1 5879.46,5467.79 5880.75,5469.23 5881.85,5470.76 5882.75,5472.4 5883.43,5474.18 5883.85,5476.12
  region net KEY1: 5794,5381.76 5784,5381.76 5783.85,5383.89 5783.43,5385.82 5782.75,5387.61 5781.85,5389.25 5780.75,5390.78 5779.47,5392.22 5776.47,5394.91 5769.46,5400.2 5765.85,5403.15 5764.1,5404.79 5762.42,5406.57 5815.57,5406.56 5813.9,5404.79 5812.15,5403.15 5808.53,5400.19 5801.52,5394.91 5798.53,5392.21 5797.25,5390.78 5796.15,5389.25 5795.24,5387.6 5794.57,5385.82 5794.14,5383.88
  region net DS_DQ: 5694,5381.76 5684,5381.76 5683.85,5383.88 5683.43,5385.82 5682.75,5387.6 5681.85,5389.25 5680.75,5390.78 5679.47,5392.22 5676.47,5394.91 5669.46,5400.2 5665.85,5403.15 5664.1,5404.79 5662.42,5406.57 5715.57,5406.56 5713.9,5404.79 5712.15,5403.15 5708.53,5400.19 5701.52,5394.91 5698.53,5392.21 5697.25,5390.78 5696.15,5389.25 5695.24,5387.6 5694.57,5385.82 5694.15,5383.88
  region net KEY1: 5621.87,4207.41 5628.94,4200.33 5627.4,4198.56 5626.22,4196.7 5625.38,4194.76 5624.83,4192.75 5624.52,4190.66 5624.43,4188.5 5624.74,4183.97 5626.22,4174.17 5626.77,4168.94 5626.87,4166.24 5626.79,4163.5 5585.03,4205.26 5587.77,4205.34 5590.47,4205.24 5595.7,4204.69 5605.5,4203.21 5610.03,4202.9 5612.19,4202.99 5614.28,4203.3 5616.29,4203.85 5618.23,4204.69 5620.09,4205.87
  region net GND: 5542.53,4373.96 5556.67,4388.1 5558.47,4386.47 5560.29,4385.15 5562.13,4384.1 5564,4383.3 5565.91,4382.72 5567.84,4382.33 5571.84,4382 5576.02,4382.07 5580.42,4382.32 5585.05,4382.52 5589.96,4382.42 5548.21,4340.66 5548.11,4345.57 5548.31,4350.21 5548.56,4354.6 5548.63,4358.78 5548.3,4362.78 5547.91,4364.72 5547.33,4366.62 5546.53,4368.49 5545.48,4370.34 5544.16,4372.16
  region net KEY2: 6036.86,4207.41 6043.94,4200.34 6042.4,4198.56 6041.22,4196.7 6040.38,4194.76 6039.83,4192.75 6039.52,4190.66 6039.43,4188.5 6039.74,4183.97 6041.22,4174.17 6041.77,4168.94 6041.87,4166.24 6041.79,4163.51 6000.03,4205.26 6002.77,4205.34 6005.47,4205.24 6010.7,4204.69 6020.5,4203.21 6025.03,4202.9 6027.19,4202.99 6029.28,4203.3 6031.29,4203.85 6033.23,4204.69 6035.09,4205.87
  region net KEY3: 6391.06,4200.33 6398.13,4207.41 6399.91,4205.87 6401.77,4204.69 6403.71,4203.85 6405.72,4203.29 6407.81,4202.99 6409.97,4202.9 6414.5,4203.21 6424.3,4204.68 6429.53,4205.24 6432.22,4205.34 6434.96,4205.26 6393.21,4163.5 6393.13,4166.24 6393.23,4168.93 6393.78,4174.17 6395.26,4183.97 6395.57,4188.49 6395.48,4190.65 6395.17,4192.74 6394.62,4194.76 6393.77,4196.69 6392.6,4198.55
  region net KEY4: 6801.06,4200.33 6808.13,4207.41 6809.91,4205.87 6811.77,4204.69 6813.7,4203.85 6815.72,4203.29 6817.81,4202.99 6819.97,4202.9 6824.49,4203.21 6834.29,4204.68 6839.53,4205.24 6842.22,4205.34 6844.96,4205.26 6803.21,4163.5 6803.13,4166.24 6803.23,4168.93 6803.78,4174.17 6805.26,4183.97 6805.57,4188.49 6805.48,4190.65 6805.17,4192.74 6804.62,4194.76 6803.77,4196.69 6802.6,4198.55
  region net GND: 6873.33,4388.1 6887.47,4373.96 6885.84,4372.16 6884.52,4370.34 6883.47,4368.5 6882.67,4366.63 6882.09,4364.72 6881.7,4362.78 6881.37,4358.79 6881.44,4354.61 6881.69,4350.21 6881.89,4345.58 6881.79,4340.67 6840.03,4382.42 6844.94,4382.52 6849.58,4382.32 6853.97,4382.07 6858.15,4382 6862.15,4382.33 6864.09,4382.72 6865.99,4383.3 6867.86,4384.1 6869.71,4385.15 6871.53,4386.47
  region net $1N63: 4712.68,3980.25 4719.75,3987.32 4721.22,3986.03 4722.76,3985.03 4724.34,3984.3 4725.98,3983.8 4727.68,3983.5 4729.42,3983.37 4733.06,3983.51 4740.93,3984.54 4745.15,3984.94 4749.53,3984.94 4715.06,3950.46 4715.06,3954.85 4715.46,3959.07 4716.49,3966.94 4716.63,3970.58 4716.5,3972.32 4716.2,3974.02 4715.7,3975.66 4714.97,3977.24 4713.97,3978.78
  region net $1N10: 4350.25,3987.32 4357.32,3980.25 4356.03,3978.77 4355.03,3977.24 4354.3,3975.66 4353.8,3974.01 4353.5,3972.32 4353.37,3970.58 4353.52,3966.93 4354.54,3959.06 4354.94,3954.85 4354.94,3950.46 4320.47,3984.94 4324.86,3984.94 4329.07,3984.54 4336.94,3983.51 4340.58,3983.37 4342.33,3983.5 4344.02,3983.8 4345.66,3984.3 4347.25,3985.03 4348.78,3986.03
  region net I2C_SCL: 5530.58,5372.74 5540.58,5372.74 5540.65,5371.42 5540.86,5370.24 5541.66,5368.18 5542.92,5366.3 5544.59,5364.33 5526.57,5364.33 5528.24,5366.3 5529.5,5368.18 5530.3,5370.24 5530.51,5371.42
  region net USART2_TX: 5894,5947.43 5884,5947.43 5883.93,5948.75 5883.72,5949.93 5882.92,5951.99 5881.66,5953.87 5879.99,5955.84 5898.01,5955.84 5896.34,5953.87 5895.08,5951.99 5894.28,5949.93 5894.07,5948.75
  region net USART2_RX: 4748.85,5479.7 4758.85,5488.63 4758.99,5485.88 4759.22,5484.59 4759.57,5483.39 4760.09,5482.33 4760.8,5481.43 4761.72,5480.71 4762.89,5480.22 4747.91,5471.29 4748.66,5475.47
  region net IR_OUT: 4194.45,5580.41 4184.45,5580.41 4184.38,5581.73 4184.17,5582.91 4183.37,5584.97 4182.11,5586.85 4180.44,5588.82 4198.46,5588.82 4196.79,5586.85 4195.53,5584.97 4194.73,5582.91 4194.52,5581.73
  region net I2C_SDA: 5430.58,5325.67 5440.58,5325.67 5440.65,5324.35 5440.86,5323.17 5441.66,5321.11 5442.92,5319.23 5444.59,5317.26 5426.57,5317.26 5428.24,5319.23 5429.5,5321.11 5430.3,5323.17 5430.51,5324.35
  region net LED_Y: 4664.53,5610.12 4654.53,5610.12 4654.46,5611.44 4654.25,5612.62 4653.45,5614.68 4652.19,5616.56 4650.52,5618.53 4668.54,5618.53 4666.87,5616.56 4665.61,5614.68 4664.81,5612.62 4664.6,5611.44
  region net DS_DQ: 5684,4891.35 5694,4891.35 5694.07,4890.03 5694.28,4888.85 5695.08,4886.79 5696.34,4884.91 5698.01,4882.94 5679.99,4882.94 5681.66,4884.91 5682.92,4886.79 5683.72,4888.85 5683.93,4890.03
  region net GND: 3703.06,4059.71 3717.21,4045.57 3715.82,4044.06 3714.68,4042.6 3712.82,4039.76 3710.96,4036.93 3709.83,4035.47 3708.44,4033.96 3691.45,4050.94 3692.96,4052.33 3694.42,4053.47 3697.26,4055.33 3700.09,4057.18 3701.55,4058.32
Bottom Layer:
  region net BUZZ: 3753.86,5693.22 3746.79,5686.14 3745.36,5687.4 3743.88,5688.37 3742.34,5689.09 3740.75,5689.59 3739.12,5689.88 3737.43,5690.02 3733.92,5689.9 3726.33,5688.94 3722.27,5688.56 3718.03,5688.57 3751.43,5721.98 3751.44,5717.74 3751.06,5713.68 3750.11,5706.09 3749.99,5702.58 3750.12,5700.89 3750.42,5699.26 3750.91,5697.67 3751.63,5696.14 3752.6,5694.65
  region net 3V3: 7051.54,4787.5 7051.54,4807.5 7066.54,4807.74 7081.54,4808.46 7081.54,4772.5 7078.3,4776.26 7074.6,4779.57 7070.49,4782.35 7066.05,4784.57 7061.36,4786.19 7056.49,4787.17 7051.54,4787.5
  region net DS_DQ: 7069.44,4870 7069.44,4880 7071.45,4880.13 7073.29,4880.53 7074.97,4881.15 7076.53,4881.99 7077.98,4883.01 7079.34,4884.2 7081.89,4886.98 7086.87,4893.51 7089.66,4896.89 7092.86,4900.1 7092.87,4849.9 7089.66,4853.11 7086.88,4856.48 7081.89,4863.01 7079.34,4865.79 7077.98,4866.98 7076.54,4868 7074.98,4868.84 7073.29,4869.47 7071.45,4869.86
  region net 3V3: 3764.07,4900.07 3749.93,4885.93 3745.2,4889.09 3740.17,4891.73 3734.88,4893.81 3729.4,4895.32 3723.79,4896.23 3718.11,4896.54 3753.46,4931.89 3753.77,4926.21 3754.68,4920.6 3756.19,4915.12 3758.27,4909.83 3760.91,4904.79 3764.07,4900.07
  region net HX_SCK: 3765.56,5035 3765.56,5025 3763.55,5024.86 3761.71,5024.47 3760.02,5023.84 3758.46,5023 3757.02,5021.98 3755.66,5020.79 3753.11,5018.01 3748.12,5011.48 3745.34,5008.11 3742.13,5004.9 3742.14,5055.1 3745.34,5051.89 3748.13,5048.51 3753.11,5041.98 3755.66,5039.2 3757.02,5038.01 3758.47,5036.99 3760.03,5036.15 3761.71,5035.52 3763.55,5035.13
  region net HX_DT: 3765.56,5135 3765.56,5125 3763.55,5124.86 3761.71,5124.47 3760.02,5123.84 3758.46,5123 3757.02,5121.98 3755.66,5120.79 3753.11,5118.01 3748.12,5111.48 3745.34,5108.11 3742.13,5104.9 3742.14,5155.1 3745.34,5151.89 3748.13,5148.51 3753.11,5141.98 3755.66,5139.2 3757.02,5138.01 3758.47,5136.99 3760.03,5136.15 3761.71,5135.52 3763.55,5135.13
  region net GND: 3683.25,3872.39 3697.39,3858.25 3696.12,3856.87 3695.06,3855.48 3694.18,3854.08 3693.46,3852.67 3692.46,3849.77 3691.91,3846.77 3691.67,3843.62 3691.61,3840.3 3691.58,3836.78 3691.43,3833.02 3658.03,3866.43 3661.78,3866.58 3665.31,3866.61 3668.63,3866.67 3671.77,3866.91 3674.78,3867.46 3677.68,3868.46 3679.09,3869.17 3680.49,3870.06 3681.88,3871.12
  region net 3V3: 5316.03,6071.18 5330.18,6057.04 5328.73,6055.46 5327.54,6053.85 5326.58,6052.23 5325.82,6050.59 5325.24,6048.92 5324.83,6047.22 5324.39,6043.72 5324.31,6040.05 5324.4,6036.19 5324.48,6032.11 5324.36,6027.78 5286.78,6065.36 5291.11,6065.48 5295.19,6065.4 5299.04,6065.31 5302.71,6065.39 5306.21,6065.83 5307.91,6066.24 5309.58,6066.82 5311.22,6067.57 5312.84,6068.54 5314.45,6069.73
  region net LED_Y: 5958.42,5992.35 5951.35,5999.43 5952.75,6001.03 5953.82,6002.71 5954.6,6004.44 5955.13,6006.24 5955.43,6008.1 5955.54,6010.03 5955.33,6014.05 5954.11,6022.74 5953.65,6027.39 5953.57,6029.78 5953.64,6032.22 5991.21,5994.63 5988.77,5994.57 5986.38,5994.64 5981.73,5995.11 5973.04,5996.33 5969.02,5996.54 5967.09,5996.43 5965.23,5996.13 5963.43,5995.6 5961.69,5994.82 5960.02,5993.75
  region net IR_OUT: 7155.32,5989.26 7148.26,5996.34 7150.54,5999.95 7152.21,6003.87 7153.23,6008.01 7153.57,6012.25 7171.23,5994.56 7166.99,5994.22 7162.85,5993.2 7158.93,5991.54 7155.32,5989.26
  region net 3V3: 6500,7231 6480,7231 6479.9,7232.91 6479.64,7234.66 6479.21,7236.28 6478.63,7237.78 6477.91,7239.18 6477.07,7240.49 6475.08,7242.93 6472.77,7245.25 6470.22,7247.58 6467.57,7250.08 6464.9,7252.87 6515.1,7252.86 6512.43,7250.07 6509.77,7247.58 6507.23,7245.24 6504.91,7242.93 6502.92,7240.49 6502.08,7239.18 6501.37,7237.78 6500.79,7236.28 6500.36,7234.66 6500.09,7232.91
  region net DS_DQ: 4351.93,5346.73 4359.01,5339.66 4357.81,5338.29 4356.87,5336.88 4356.18,5335.42 4355.69,5333.92 4355.4,5332.37 4355.26,5330.77 4355.34,5327.45 4356.2,5320.29 4356.54,5316.45 4356.54,5312.44 4324.71,5344.25 4328.72,5344.26 4332.56,5343.92 4339.73,5343.06 4343.05,5342.98 4344.64,5343.12 4346.19,5343.41 4347.69,5343.9 4349.15,5344.59 4350.57,5345.53
  region net 3V3: 4285.75,4792.5 4285.75,4812.5 4289.16,4812.77 4292.12,4813.54 4294.76,4814.75 4297.17,4816.32 4299.46,4818.2 4301.75,4820.32 4306.75,4825 4306.75,4780 4301.75,4784.68 4299.47,4786.79 4297.17,4788.67 4294.76,4790.25 4292.13,4791.45 4289.16,4792.22
  region net 3V3: 4370.91,4807.5 4363.41,4787.5 4360.14,4787.25 4357.29,4786.55 4354.74,4785.48 4352.38,4784.11 4347.73,4780.73 4345.22,4778.88 4342.41,4777.01 4349.91,4821.38 4354.45,4815.91 4356.69,4813.54 4359.01,4811.5 4361.51,4809.82 4364.27,4808.56 4367.38,4807.77
  region net LED_R: 4461.94,5484.92 4469.01,5477.84 4467.81,5476.48 4466.88,5475.06 4466.18,5473.6 4465.7,5472.1 4465.4,5470.55 4465.26,5468.96 4465.34,5465.64 4466.2,5458.47 4466.55,5454.63 4466.54,5450.62 4434.72,5482.44 4438.73,5482.45 4442.57,5482.11 4449.73,5481.25 4453.06,5481.16 4454.65,5481.3 4456.2,5481.6 4457.7,5482.08 4459.16,5482.78 4460.57,5483.71
  region net I2C_SCL: 4581.93,5341.73 4589.01,5334.66 4587.81,5333.3 4586.87,5331.88 4586.18,5330.42 4585.69,5328.92 4585.4,5327.37 4585.26,5325.78 4585.34,5322.45 4586.2,5315.29 4586.54,5311.45 4586.54,5307.44 4554.71,5339.25 4558.72,5339.26 4562.56,5338.92 4569.73,5338.06 4573.05,5337.98 4574.64,5338.12 4576.19,5338.41 4577.69,5338.9 4579.15,5339.59 4580.57,5340.53
  region net 3V3: 4515.75,4787.5 4515.75,4807.5 4519.16,4807.77 4522.12,4808.54 4524.76,4809.75 4527.17,4811.32 4529.46,4813.2 4531.75,4815.32 4536.75,4820 4536.75,4775 4531.75,4779.68 4529.47,4781.79 4527.17,4783.67 4524.76,4785.25 4522.13,4786.45 4519.16,4787.22
  region net 3V3: 4597.44,4807.5 4597.44,4787.5 4594.03,4787.22 4591.06,4786.45 4588.43,4785.25 4586.02,4783.67 4583.72,4781.79 4581.44,4779.68 4576.44,4775 4576.44,4820 4581.44,4815.32 4583.73,4813.2 4586.02,4811.32 4588.43,4809.75 4591.07,4808.54 4594.03,4807.77
  region net I2C_SDA: 4817.43,5314.32 4817.44,5304.32 4815.63,5304.2 4813.97,5303.86 4812.44,5303.32 4811.04,5302.6 4809.73,5301.71 4808.5,5300.69 4806.21,5298.28 4801.76,5292.6 4799.28,5289.64 4796.44,5286.81 4796.43,5331.81 4799.28,5328.99 4801.75,5326.03 4806.21,5320.35 4808.5,5317.95 4809.73,5316.92 4811.03,5316.03 4812.44,5315.31 4813.96,5314.77 4815.62,5314.43
  region net 3V3: 4735.75,4787.5 4735.75,4807.5 4739.16,4807.77 4742.12,4808.54 4744.76,4809.75 4747.17,4811.32 4749.46,4813.2 4751.75,4815.32 4756.75,4820 4756.75,4775 4751.75,4779.68 4749.47,4781.79 4747.17,4783.67 4744.76,4785.25 4742.13,4786.45 4739.16,4787.22
  region net 3V3: 4817.44,4807.5 4817.44,4787.5 4814.03,4787.22 4811.06,4786.45 4808.43,4785.25 4806.02,4783.67 4803.72,4781.79 4801.44,4779.68 4796.44,4775 4796.44,4820 4801.44,4815.32 4803.73,4813.2 4806.02,4811.32 4808.43,4809.75 4811.07,4808.54 4814.03,4807.77
  region net USART2_TX: 4208.79,7231.32 4201.72,7224.25 4200.21,7225.57 4198.63,7226.59 4196.99,7227.35 4195.3,7227.85 4193.55,7228.15 4191.75,7228.28 4187.98,7228.11 4179.84,7227.02 4175.48,7226.6 4170.95,7226.6 4206.44,7262.1 4206.44,7257.56 4206.02,7253.21 4204.93,7245.06 4204.76,7241.3 4204.89,7239.49 4205.19,7237.75 4205.69,7236.05 4206.44,7234.42 4207.47,7232.84
  region net GND: 7140.76,5420.01 7140.76,5440.01 7142.91,5440.1 7144.89,5440.39 7146.71,5440.86 7148.41,5441.48 7150,5442.26 7151.49,5443.17 7154.28,5445.33 7156.93,5447.87 7159.59,5450.66 7162.42,5453.6 7165.56,5456.58 7165.56,5403.43 7162.41,5406.41 7159.59,5409.35 7156.93,5412.14 7154.28,5414.68 7151.49,5416.84 7149.99,5417.75 7148.41,5418.53 7146.71,5419.15 7144.88,5419.62 7142.9,5419.91
  region net GND: 7137.24,5440.01 7137.24,5420.01 7135.09,5419.91 7133.12,5419.62 7131.29,5419.15 7129.59,5418.53 7128,5417.75 7126.51,5416.84 7123.72,5414.68 7121.07,5412.14 7118.41,5409.35 7115.58,5406.41 7112.44,5403.43 7112.43,5456.58 7115.58,5453.6 7118.41,5450.66 7121.07,5447.87 7123.72,5445.33 7126.5,5443.17 7128,5442.26 7129.59,5441.48 7131.28,5440.86 7133.11,5440.39 7135.09,5440.1
  region net HX_DT: 6751.35,5460.58 6758.42,5467.65 6760.03,5466.25 6761.7,5465.18 6763.44,5464.4 6765.24,5463.87 6767.1,5463.57 6769.02,5463.46 6773.04,5463.67 6781.73,5464.89 6786.38,5465.36 6788.78,5465.43 6791.22,5465.37 6753.64,5427.78 6753.57,5430.22 6753.64,5432.62 6754.11,5437.27 6755.33,5445.96 6755.54,5449.98 6755.43,5451.9 6755.13,5453.76 6754.6,5455.56 6753.82,5457.3 6752.75,5458.97
  region net HX_SCK: 6658.42,5392.36 6651.35,5399.43 6652.75,5401.04 6653.82,5402.71 6654.6,5404.44 6655.13,5406.24 6655.43,5408.11 6655.54,5410.03 6655.32,5414.05 6654.11,5422.74 6653.64,5427.39 6653.57,5429.79 6653.64,5432.23 6691.21,5394.64 6688.77,5394.57 6686.38,5394.65 6681.73,5395.11 6673.04,5396.33 6669.02,5396.54 6667.09,5396.43 6665.23,5396.13 6663.43,5395.61 6661.69,5394.83 6660.02,5393.75
  region net LED_R: 6551.35,5460.58 6558.42,5467.65 6560.03,5466.25 6561.7,5465.18 6563.44,5464.4 6565.24,5463.87 6567.1,5463.57 6569.02,5463.46 6573.04,5463.67 6581.74,5464.89 6586.38,5465.36 6588.78,5465.43 6591.22,5465.37 6553.64,5427.78 6553.57,5430.22 6553.64,5432.62 6554.11,5437.27 6555.33,5445.96 6555.54,5449.98 6555.43,5451.9 6555.13,5453.77 6554.6,5455.57 6553.82,5457.3 6552.75,5458.97
  region net BUZZ: 6451.35,5460.58 6458.42,5467.65 6460.03,5466.25 6461.7,5465.18 6463.44,5464.4 6465.24,5463.87 6467.1,5463.57 6469.02,5463.46 6473.04,5463.67 6481.74,5464.89 6486.38,5465.36 6488.78,5465.43 6491.22,5465.37 6453.64,5427.78 6453.57,5430.22 6453.64,5432.62 6454.11,5437.27 6455.33,5445.96 6455.54,5449.98 6455.43,5451.9 6455.13,5453.77 6454.6,5455.57 6453.82,5457.3 6452.75,5458.97
  region net USART2_RX: 5951.35,5460.58 5958.43,5467.65 5960.03,5466.25 5961.7,5465.18 5963.44,5464.4 5965.24,5463.87 5967.1,5463.57 5969.02,5463.46 5973.04,5463.68 5981.74,5464.89 5986.39,5465.36 5988.78,5465.43 5991.22,5465.37 5953.64,5427.78 5953.57,5430.22 5953.64,5432.62 5954.11,5437.27 5955.33,5445.96 5955.54,5449.98 5955.43,5451.9 5955.13,5453.77 5954.6,5455.57 5953.82,5457.3 5952.75,5458.97
  region net DS_DQ: 5658.42,5392.36 5651.35,5399.43 5652.75,5401.03 5653.82,5402.71 5654.6,5404.44 5655.13,5406.24 5655.43,5408.1 5655.54,5410.03 5655.33,5414.05 5654.11,5422.74 5653.64,5427.39 5653.57,5429.78 5653.64,5432.22 5691.22,5394.64 5688.78,5394.57 5686.38,5394.65 5681.73,5395.11 5673.04,5396.33 5669.02,5396.54 5667.1,5396.43 5665.23,5396.13 5663.43,5395.61 5661.7,5394.83 5660.03,5393.75
  region net GND: 5597.5,4296.04 5577.5,4296.04 5577.36,4297.52 5576.97,4298.92 5576.35,4300.25 5575.52,4301.54 5573.32,4303.99 5570.58,4306.38 5564.23,4311.31 5560.99,4314.05 5557.97,4317.09 5617.03,4317.09 5614.01,4314.04 5610.77,4311.31 5604.41,4306.37 5601.67,4303.99 5599.48,4301.54 5598.65,4300.25 5598.03,4298.92 5597.63,4297.52
  region net GND: 5971.67,4298.16 5957.53,4312.3 5959.16,4314.1 5960.48,4315.92 5961.53,4317.77 5962.33,4319.64 5962.91,4321.54 5963.3,4323.48 5963.63,4327.47 5963.56,4331.65 5963.31,4336.05 5963.11,4340.69 5963.21,4345.6 6004.97,4303.84 6000.06,4303.74 5995.42,4303.94 5991.02,4304.19 5986.84,4304.26 5982.85,4303.93 5980.91,4303.54 5979.01,4302.96 5977.13,4302.16 5975.29,4301.11 5973.47,4299.79
  region net GND: 6047.47,4312.3 6033.33,4298.16 6031.53,4299.79 6029.71,4301.11 6027.86,4302.16 6025.99,4302.96 6024.09,4303.54 6022.15,4303.93 6018.15,4304.26 6013.97,4304.19 6009.58,4303.94 6004.94,4303.74 6000.03,4303.84 6041.79,4345.59 6041.89,4340.68 6041.69,4336.04 6041.44,4331.65 6041.37,4327.47 6041.7,4323.47 6042.09,4321.54 6042.67,4319.63 6043.47,4317.76 6044.52,4315.92 6045.84,4314.1
  region net GND: 6401.67,4298.16 6387.53,4312.3 6389.16,4314.1 6390.48,4315.92 6391.53,4317.77 6392.33,4319.64 6392.91,4321.54 6393.3,4323.48 6393.63,4327.47 6393.56,4331.65 6393.31,4336.05 6393.11,4340.69 6393.21,4345.6 6434.96,4303.84 6430.05,4303.74 6425.42,4303.94 6421.02,4304.19 6416.84,4304.26 6412.85,4303.93 6410.91,4303.54 6409.01,4302.96 6407.13,4302.16 6405.29,4301.11 6403.47,4299.79
  region net GND: 6477.47,4312.3 6463.32,4298.16 6461.52,4299.79 6459.7,4301.11 6457.86,4302.16 6455.99,4302.96 6454.09,4303.54 6452.15,4303.93 6448.15,4304.26 6443.97,4304.19 6439.58,4303.94 6434.94,4303.74 6430.03,4303.84 6471.79,4345.59 6471.89,4340.68 6471.69,4336.04 6471.44,4331.65 6471.37,4327.47 6471.7,4323.47 6472.09,4321.53 6472.67,4319.63 6473.47,4317.76 6474.52,4315.92 6475.84,4314.1
  region net GND: 6811.67,4298.16 6797.53,4312.3 6799.16,4314.1 6800.48,4315.92 6801.53,4317.77 6802.33,4319.64 6802.91,4321.54 6803.3,4323.48 6803.63,4327.48 6803.56,4331.66 6803.31,4336.05 6803.11,4340.69 6803.21,4345.6 6844.96,4303.84 6840.05,4303.74 6835.42,4303.94 6831.02,4304.19 6826.84,4304.26 6822.85,4303.93 6820.91,4303.54 6819,4302.96 6817.13,4302.16 6815.29,4301.11 6813.47,4299.79
  region net GND: 4809.14,3976.72 4823.28,3990.86 4824.71,3989.54 4826.16,3988.45 4827.61,3987.54 4829.09,3986.82 4832.1,3985.82 4835.23,3985.3 4838.51,3985.1 4841.97,3985.08 4845.63,3985.07 4849.53,3984.94 4815.06,3950.46 4814.93,3954.36 4814.92,3958.03 4814.9,3961.48 4814.7,3964.76 4814.18,3967.9 4813.18,3970.91 4812.46,3972.39 4811.55,3973.84 4810.46,3975.28
  region net GND: 4871.72,3990.86 4885.86,3976.71 4884.55,3975.28 4883.45,3973.84 4882.54,3972.39 4881.82,3970.91 4880.82,3967.9 4880.3,3964.76 4880.1,3961.48 4880.08,3958.03 4880.07,3954.36 4879.94,3950.46 4845.47,3984.94 4849.37,3985.07 4853.03,3985.08 4856.49,3985.1 4859.77,3985.3 4862.9,3985.82 4865.92,3986.82 4867.39,3987.54 4868.85,3988.45 4870.29,3989.54
  region net GND: 4178.25,3942.5 4178.25,3962.5 4180.19,3962.58 4181.99,3962.82 4183.66,3963.22 4185.21,3963.74 4188.05,3965.17 4190.64,3967.02 4193.09,3969.2 4195.56,3971.62 4198.15,3974.21 4201,3976.87 4201,3928.12 4198.15,3930.79 4195.56,3933.37 4193.1,3935.8 4190.64,3937.98 4188.05,3939.83 4185.21,3941.25 4183.66,3941.78 4181.99,3942.17 4180.19,3942.42
  region net GND: 4246.72,3990.86 4260.86,3976.71 4259.55,3975.28 4258.45,3973.84 4257.54,3972.38 4256.82,3970.91 4255.82,3967.89 4255.3,3964.76 4255.1,3961.48 4255.08,3958.03 4255.07,3954.36 4254.94,3950.46 4220.47,3984.94 4224.37,3985.07 4228.03,3985.08 4231.49,3985.1 4234.77,3985.3 4237.9,3985.82 4240.92,3986.82 4242.39,3987.54 4243.85,3988.45 4245.29,3989.54
  region net I2C_SCL: 5519.23,5351.39 5519.23,5361.39 5520.54,5361.46 5521.72,5361.66 5523.78,5362.46 5525.67,5363.73 5527.64,5365.39 5527.64,5347.38 5525.67,5349.04 5523.78,5350.31 5521.72,5351.11 5520.54,5351.31
  region net USART2_TX: 5872.65,5958.78 5872.65,5968.78 5873.96,5968.85 5875.14,5969.06 5877.2,5969.86 5879.09,5971.13 5881.05,5972.79 5881.05,5954.78 5879.09,5956.44 5877.2,5957.7 5875.14,5958.5 5873.96,5958.71
  region net USART2_RX: 4765.95,5482.05 4773.02,5474.98 4772.41,5474.24 4772.01,5473.47 4771.67,5471.81 4771.62,5467.91 4758.88,5480.65 4762.77,5480.7 4764.44,5481.05 4765.21,5481.45
  region net IR_OUT: 4205.8,5601.76 4205.8,5591.76 4204.49,5591.69 4203.31,5591.48 4201.25,5590.68 4199.36,5589.42 4197.4,5587.76 4197.4,5605.77 4199.36,5604.11 4201.25,5602.84 4203.31,5602.04 4204.49,5601.84
  region net I2C_SDA: 5419.23,5304.32 5419.23,5314.32 5420.54,5314.39 5421.72,5314.6 5423.78,5315.4 5425.67,5316.66 5427.64,5318.32 5427.64,5300.31 5425.67,5301.97 5423.78,5303.24 5421.72,5304.04 5420.54,5304.24
  region net LED_Y: 4675.88,5631.47 4675.88,5621.47 4674.57,5621.4 4673.39,5621.19 4671.33,5620.39 4669.44,5619.13 4667.47,5617.47 4667.47,5635.48 4669.44,5633.82 4671.33,5632.55 4673.39,5631.75 4674.57,5631.55
  region net DS_DQ: 5705.35,4880 5705.35,4870 5704.03,4869.93 5702.86,4869.72 5700.8,4868.92 5698.91,4867.65 5696.94,4865.99 5696.94,4884 5698.91,4882.34 5700.8,4881.08 5702.86,4880.28 5704.03,4880.07
  region net GND: 3717.21,4039.33 3703.06,4025.19 3701.55,4026.58 3700.09,4027.71 3697.26,4029.57 3694.42,4031.43 3692.96,4032.57 3691.45,4033.96 3708.44,4050.94 3709.83,4049.43 3710.96,4047.97 3712.82,4045.13 3714.68,4042.3 3715.82,4040.84
  region net GND: 3806,3942.5 3797.97,3942.18 3789.98,3941.21 3782.11,3939.6 3774.38,3937.37 3766.86,3934.52 3759.59,3931.08 3752.63,3927.06 3746,3922.5 3736,3952.5 3746,3982.5 3752.63,3977.94 3759.59,3973.92 3766.86,3970.48 3774.38,3967.63 3782.11,3965.4 3789.98,3963.79 3797.97,3962.82 3806,3962.5 3806,3942.5

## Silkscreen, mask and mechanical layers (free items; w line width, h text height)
Top Silkscreen Layer:
  text "2352500401谢玲  / 基于单片机的输液状态WiFi监测装置设计" at 5225,3640 h120

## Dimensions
4822.84,7260 to 4822.84,6570 on Document Layer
